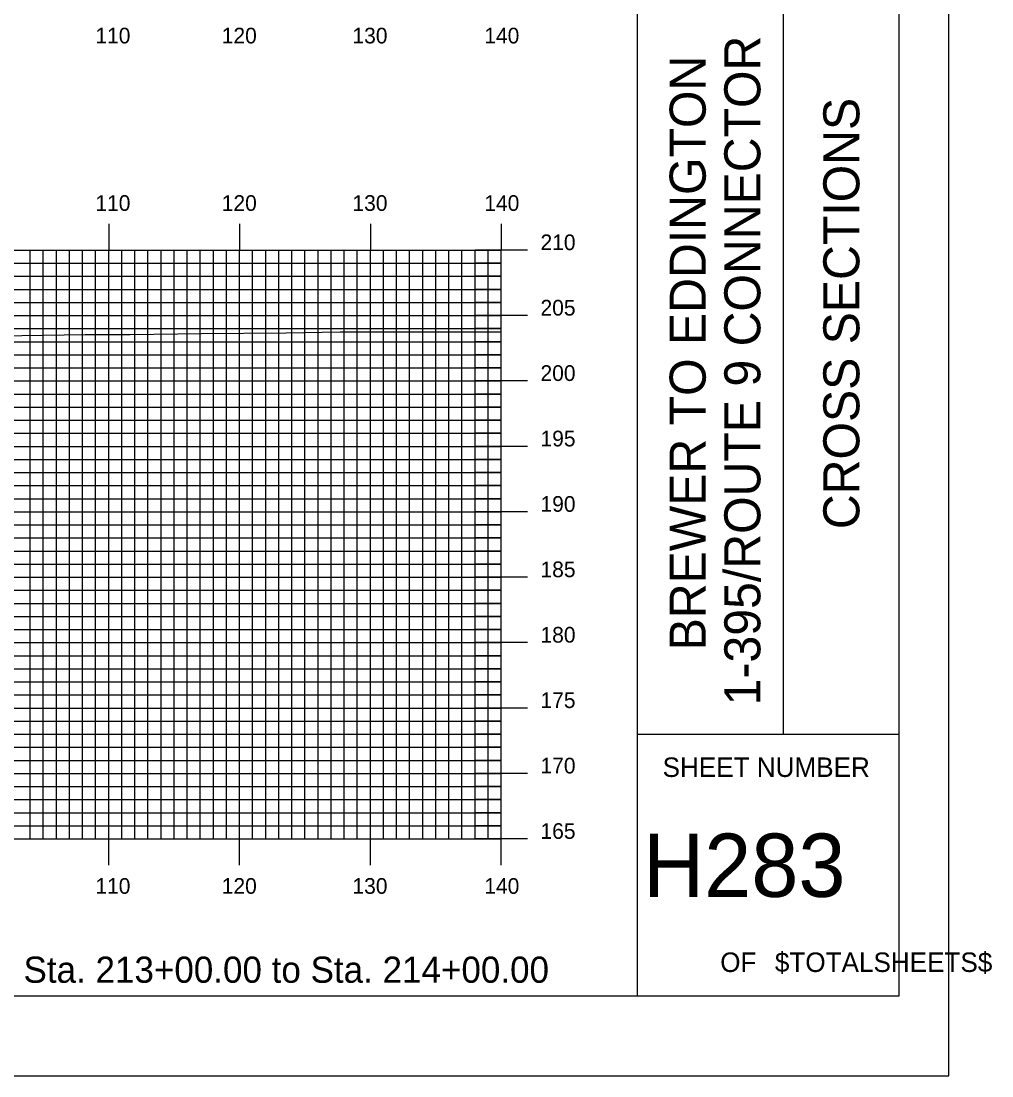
# Model space of a CAD drawing. Extents: x 1795633 to 1795976, y 442591 to 442811.
# Drawn here: x 1795902.2 to 1795976.4, y 442590.5 to 442671.2 of the extents above; entities that cross this region are included whole.
import ezdxf

# ---------------------------------------------------------------- set-up
doc = ezdxf.new("R2010")
doc.units = 0
for name, color, linetype in [('BORDER', 7, 'Continuous'), ('H_V ANNOTATION', 7, 'Continuous'), ('MAJOR', 7, 'Continuous'), ('MINOR', 7, 'Continuous'), ('PLOT BOUNDARY', 7, 'Continuous'), ('S_Roadway_Centerline', 7, 'Continuous')]:
    doc.layers.add(name, color=color, linetype=linetype)

msp = doc.modelspace()

# ---------------------------------------------------------------- linework, layer by layer
at = {"layer": 'BORDER'}
for p, q in [((1795949.279, 442596.665), (1795949.279, 442806.665)), ((1795960.461, 442616.671), (1795960.461, 442686.671)), ((1795949.279, 442616.671), (1795969.279, 442616.671))]:
    msp.add_line(p, q, dxfattribs=at)
msp.add_lwpolyline([(1795649.279, 442596.665), (1795969.279, 442596.665), (1795969.279, 442806.665), (1795649.279, 442806.665)], close=True, dxfattribs=at)
at = {"layer": 'MAJOR'}
for p, q in [((1795908.879, 442655.669), (1795908.879, 442653.665)), ((1795918.879, 442655.669), (1795918.879, 442653.665)), ((1795928.879, 442655.669), (1795928.879, 442653.665)), ((1795938.879, 442655.669), (1795938.879, 442653.665)), ((1795658.879, 442653.665), (1795938.879, 442653.665)), ((1795658.879, 442653.665), (1795938.879, 442653.665)), ((1795908.879, 442608.665), (1795908.879, 442653.665)), ((1795918.879, 442608.665), (1795918.879, 442653.665)), ((1795928.879, 442608.665), (1795928.879, 442653.665)), ((1795940.883, 442653.665), (1795936.875, 442653.665)), ((1795938.879, 442608.665), (1795938.879, 442653.665)), ((1795938.879, 442608.665), (1795938.879, 442653.665)), ((1795658.879, 442648.665), (1795938.879, 442648.665)), ((1795940.883, 442648.665), (1795936.875, 442648.665)), ((1795658.879, 442643.665), (1795938.879, 442643.665)), ((1795940.883, 442643.665), (1795936.875, 442643.665)), ((1795658.879, 442638.665), (1795938.879, 442638.665)), ((1795940.883, 442638.665), (1795936.875, 442638.665)), ((1795658.879, 442633.665), (1795938.879, 442633.665)), ((1795940.883, 442633.665), (1795936.875, 442633.665)), ((1795658.879, 442628.665), (1795938.879, 442628.665)), ((1795940.883, 442628.665), (1795936.875, 442628.665)), ((1795658.879, 442623.665), (1795938.879, 442623.665)), ((1795940.883, 442623.665), (1795936.875, 442623.665)), ((1795658.879, 442618.665), (1795938.879, 442618.665)), ((1795940.883, 442618.665), (1795936.875, 442618.665)), ((1795658.879, 442613.665), (1795938.879, 442613.665)), ((1795940.883, 442613.665), (1795936.875, 442613.665)), ((1795658.879, 442608.665), (1795938.879, 442608.665)), ((1795658.879, 442608.665), (1795938.879, 442608.665)), ((1795908.879, 442606.661), (1795908.879, 442608.665)), ((1795918.879, 442606.661), (1795918.879, 442608.665)), ((1795928.879, 442606.661), (1795928.879, 442608.665)), ((1795940.883, 442608.665), (1795936.875, 442608.665)), ((1795938.879, 442606.661), (1795938.879, 442608.665))]:
    msp.add_line(p, q, dxfattribs=at)
at = {"layer": 'MINOR'}
for p, q in [((1795902.879, 442608.665), (1795902.879, 442653.665)), ((1795903.879, 442608.665), (1795903.879, 442653.665)), ((1795904.879, 442608.665), (1795904.879, 442653.665)), ((1795905.879, 442608.665), (1795905.879, 442653.665)), ((1795906.879, 442608.665), (1795906.879, 442653.665)), ((1795907.879, 442608.665), (1795907.879, 442653.665)), ((1795909.879, 442608.665), (1795909.879, 442653.665)), ((1795910.879, 442608.665), (1795910.879, 442653.665)), ((1795911.879, 442608.665), (1795911.879, 442653.665)), ((1795912.879, 442608.665), (1795912.879, 442653.665)), ((1795913.879, 442608.665), (1795913.879, 442653.665)), ((1795914.879, 442608.665), (1795914.879, 442653.665)), ((1795915.879, 442608.665), (1795915.879, 442653.665)), ((1795916.879, 442608.665), (1795916.879, 442653.665)), ((1795917.879, 442608.665), (1795917.879, 442653.665)), ((1795919.879, 442608.665), (1795919.879, 442653.665)), ((1795920.879, 442608.665), (1795920.879, 442653.665)), ((1795921.879, 442608.665), (1795921.879, 442653.665)), ((1795922.879, 442608.665), (1795922.879, 442653.665)), ((1795923.879, 442608.665), (1795923.879, 442653.665)), ((1795924.879, 442608.665), (1795924.879, 442653.665)), ((1795925.879, 442608.665), (1795925.879, 442653.665)), ((1795926.879, 442608.665), (1795926.879, 442653.665)), ((1795927.879, 442608.665), (1795927.879, 442653.665)), ((1795929.879, 442608.665), (1795929.879, 442653.665)), ((1795930.879, 442608.665), (1795930.879, 442653.665)), ((1795931.879, 442608.665), (1795931.879, 442653.665)), ((1795932.879, 442608.665), (1795932.879, 442653.665)), ((1795933.879, 442608.665), (1795933.879, 442653.665)), ((1795934.879, 442608.665), (1795934.879, 442653.665)), ((1795935.879, 442608.665), (1795935.879, 442653.665)), ((1795936.879, 442608.665), (1795936.879, 442653.665)), ((1795937.879, 442608.665), (1795937.879, 442653.665)), ((1795658.879, 442652.665), (1795938.879, 442652.665)), ((1795938.879, 442652.665), (1795936.875, 442652.665)), ((1795658.879, 442651.665), (1795938.879, 442651.665)), ((1795938.879, 442651.665), (1795936.875, 442651.665)), ((1795658.879, 442650.665), (1795938.879, 442650.665)), ((1795938.879, 442650.665), (1795936.875, 442650.665)), ((1795658.879, 442649.665), (1795938.879, 442649.665)), ((1795938.879, 442649.665), (1795936.875, 442649.665)), ((1795658.879, 442647.665), (1795938.879, 442647.665)), ((1795938.879, 442647.665), (1795936.875, 442647.665)), ((1795658.879, 442646.665), (1795938.879, 442646.665)), ((1795938.879, 442646.665), (1795936.875, 442646.665)), ((1795658.879, 442645.665), (1795938.879, 442645.665)), ((1795938.879, 442645.665), (1795936.875, 442645.665)), ((1795658.879, 442644.665), (1795938.879, 442644.665)), ((1795938.879, 442644.665), (1795936.875, 442644.665)), ((1795658.879, 442642.665), (1795938.879, 442642.665)), ((1795938.879, 442642.665), (1795936.875, 442642.665)), ((1795658.879, 442641.665), (1795938.879, 442641.665)), ((1795938.879, 442641.665), (1795936.875, 442641.665)), ((1795658.879, 442640.665), (1795938.879, 442640.665)), ((1795938.879, 442640.665), (1795936.875, 442640.665)), ((1795658.879, 442639.665), (1795938.879, 442639.665)), ((1795938.879, 442639.665), (1795936.875, 442639.665)), ((1795658.879, 442637.665), (1795938.879, 442637.665)), ((1795938.879, 442637.665), (1795936.875, 442637.665)), ((1795658.879, 442636.665), (1795938.879, 442636.665)), ((1795938.879, 442636.665), (1795936.875, 442636.665)), ((1795658.879, 442635.665), (1795938.879, 442635.665)), ((1795938.879, 442635.665), (1795936.875, 442635.665)), ((1795658.879, 442634.665), (1795938.879, 442634.665)), ((1795938.879, 442634.665), (1795936.875, 442634.665)), ((1795658.879, 442632.665), (1795938.879, 442632.665)), ((1795938.879, 442632.665), (1795936.875, 442632.665)), ((1795658.879, 442631.665), (1795938.879, 442631.665)), ((1795938.879, 442631.665), (1795936.875, 442631.665)), ((1795658.879, 442630.665), (1795938.879, 442630.665)), ((1795938.879, 442630.665), (1795936.875, 442630.665)), ((1795658.879, 442629.665), (1795938.879, 442629.665)), ((1795938.879, 442629.665), (1795936.875, 442629.665)), ((1795658.879, 442627.665), (1795938.879, 442627.665)), ((1795938.879, 442627.665), (1795936.875, 442627.665)), ((1795658.879, 442626.665), (1795938.879, 442626.665)), ((1795938.879, 442626.665), (1795936.875, 442626.665)), ((1795658.879, 442625.665), (1795938.879, 442625.665)), ((1795938.879, 442625.665), (1795936.875, 442625.665)), ((1795658.879, 442624.665), (1795938.879, 442624.665)), ((1795938.879, 442624.665), (1795936.875, 442624.665)), ((1795658.879, 442622.665), (1795938.879, 442622.665)), ((1795938.879, 442622.665), (1795936.875, 442622.665)), ((1795658.879, 442621.665), (1795938.879, 442621.665)), ((1795938.879, 442621.665), (1795936.875, 442621.665)), ((1795658.879, 442620.665), (1795938.879, 442620.665)), ((1795938.879, 442620.665), (1795936.875, 442620.665)), ((1795658.879, 442619.665), (1795938.879, 442619.665)), ((1795938.879, 442619.665), (1795936.875, 442619.665)), ((1795658.879, 442617.665), (1795938.879, 442617.665)), ((1795938.879, 442617.665), (1795936.875, 442617.665)), ((1795658.879, 442616.665), (1795938.879, 442616.665)), ((1795938.879, 442616.665), (1795936.875, 442616.665)), ((1795658.879, 442615.665), (1795938.879, 442615.665)), ((1795938.879, 442615.665), (1795936.875, 442615.665)), ((1795658.879, 442614.665), (1795938.879, 442614.665)), ((1795938.879, 442614.665), (1795936.875, 442614.665)), ((1795658.879, 442612.665), (1795938.879, 442612.665)), ((1795938.879, 442612.665), (1795936.875, 442612.665)), ((1795658.879, 442611.665), (1795938.879, 442611.665)), ((1795938.879, 442611.665), (1795936.875, 442611.665)), ((1795658.879, 442610.665), (1795938.879, 442610.665)), ((1795938.879, 442610.665), (1795936.875, 442610.665)), ((1795658.879, 442609.665), (1795938.879, 442609.665)), ((1795938.879, 442609.665), (1795936.875, 442609.665))]:
    msp.add_line(p, q, dxfattribs=at)
at = {"layer": 'PLOT BOUNDARY'}
msp.add_lwpolyline([(1795633.092, 442590.547), (1795973.092, 442590.547), (1795973.092, 442810.547), (1795633.092, 442810.547)], close=True, dxfattribs=at)
at = {"layer": 'S_Roadway_Centerline'}
msp.add_lwpolyline([(1795853.354, 442646.443), (1795862.992, 442646.707), (1795868.789, 442646.817), (1795877.249, 442646.871), (1795894.131, 442647.02), (1795907.074, 442647.226), (1795910.518, 442647.211), (1795915.971, 442647.293), (1795922.426, 442647.336), (1795926.579, 442647.431), (1795938.879, 442647.428)], dxfattribs=at)

# ---------------------------------------------------------------- texts
at = {"layer": 'BORDER'}
for s, p in [('1-395/ROUTE 9 CONNECTOR', (1795958.682, 442618.865)), ('BREWER TO EDDINGTON', (1795954.503, 442623.074)), ('CROSS SECTIONS', (1795966.248, 442632.339))]:
    msp.add_text(s, height=2.75575, rotation=90, dxfattribs=at).set_placement(p)
for s, height, p in [('SHEET NUMBER', 1.49054, (1795951.21, 442613.398)), ('H283', 4.8388, (1795949.718, 442604.23)), ('OF', 1.4905, (1795955.613, 442598.491)), ('$TOTALSHEETS$', 1.49054, (1795959.792, 442598.491))]:
    msp.add_text(s, height=height, dxfattribs=at).set_placement(p)
at = {"layer": 'H_V ANNOTATION'}
for s, height, p in [('110', 1.2, (1795907.862, 442669.465)), ('120', 1.2, (1795917.52, 442669.465)), ('130', 1.2, (1795927.509, 442669.465)), ('140', 1.2, (1795937.584, 442669.465)), ('110', 1.2, (1795907.862, 442656.665)), ('120', 1.2, (1795917.52, 442656.665)), ('130', 1.2, (1795927.509, 442656.665)), ('140', 1.2, (1795937.584, 442656.665)), ('210', 1.2, (1795941.879, 442653.665)), ('205', 1.2, (1795941.879, 442648.665)), ('200', 1.2, (1795941.879, 442643.665)), ('195', 1.2, (1795941.879, 442638.665)), ('190', 1.2, (1795941.879, 442633.665)), ('185', 1.2, (1795941.879, 442628.665)), ('180', 1.2, (1795941.879, 442623.665)), ('175', 1.2, (1795941.879, 442618.665)), ('170', 1.2, (1795941.879, 442613.665)), ('165', 1.2, (1795941.879, 442608.665)), ('110', 1.2, (1795907.862, 442604.465)), ('120', 1.2, (1795917.52, 442604.465)), ('130', 1.2, (1795927.509, 442604.465)), ('140', 1.2, (1795937.584, 442604.465)), ('Sta. 213+00.00 to Sta. 214+00.00', 2.0004, (1795902.37, 442597.665))]:
    msp.add_text(s, height=height, dxfattribs=at).set_placement(p)

doc.saveas('drawing.dxf')
